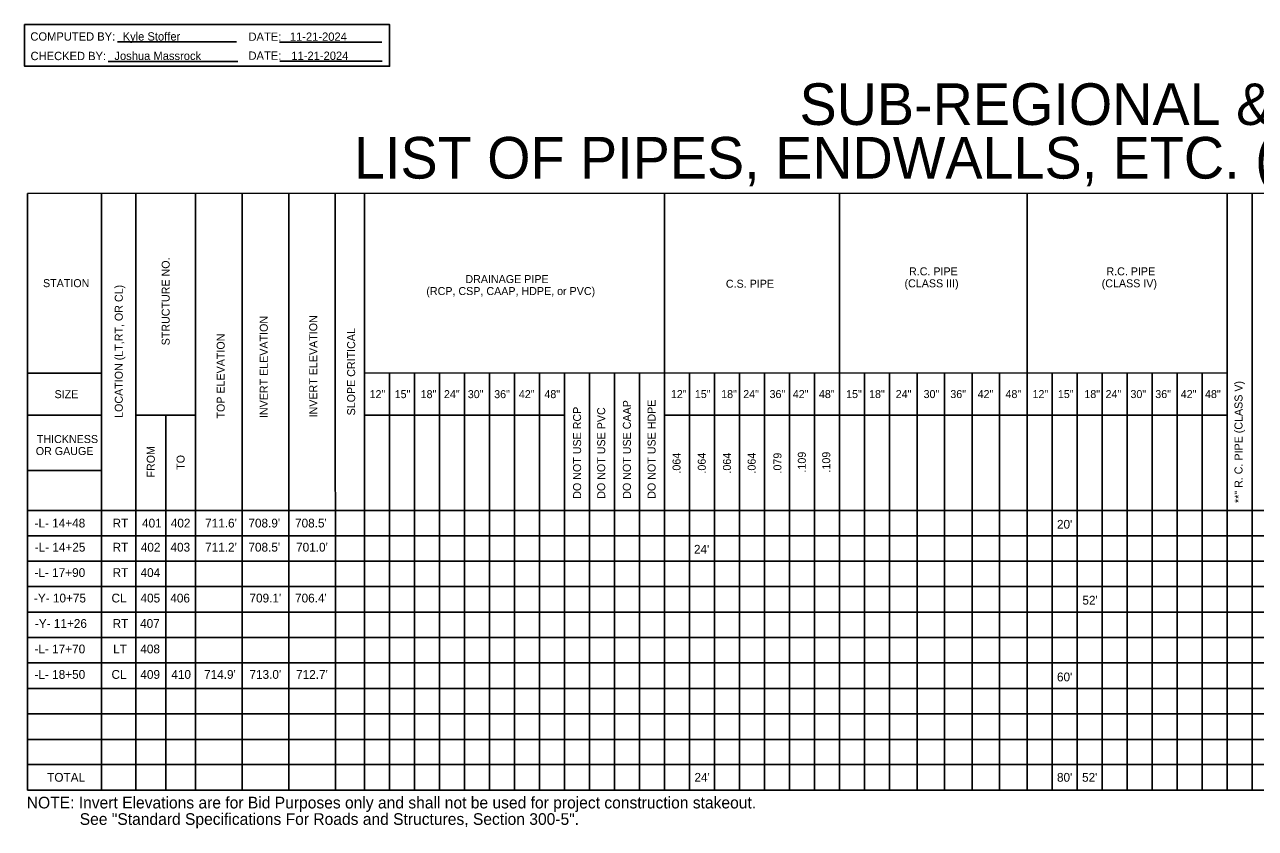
# Model space of a CAD drawing. Extents: x 3532015 to 3532162, y 657889 to 657939.
# Drawn here: x 3532014.8 to 3532088.6, y 657888.8 to 657937.1 of the extents above; entities that cross this region are included whole.
import ezdxf

# ---------------------------------------------------------------- set-up
doc = ezdxf.new("R2010")
doc.units = 0
for name, color, linetype in [('Sheet Block Check By Box CELL', 7, 'Continuous'), ('Sheet Data Field CELL', 7, 'Continuous'), ('Sheet Pipe Summary CELL', 7, 'Continuous'), ('Sheet Pipe Summary Grid CELL', 7, 'Continuous'), ('Sheet Summary Guardrail CELL', 7, 'Continuous')]:
    doc.layers.add(name, color=color, linetype=linetype)

msp = doc.modelspace()

# ---------------------------------------------------------------- linework, layer by layer
at = {"layer": 'Sheet Block Check By Box CELL'}
for p, q in [((3532020.363, 657936.023), (3532027.518, 657936.023)), ((3532030.098, 657936.008), (3532036.238, 657936.008)), ((3532019.818, 657934.853), (3532027.588, 657934.853)), ((3532030.113, 657934.858), (3532036.253, 657934.858))]:
    msp.add_line(p, q, dxfattribs=at)
msp.add_lwpolyline([(3532014.798, 657937.063), (3532036.698, 657937.063), (3532036.698, 657934.563), (3532014.798, 657934.563)], close=True, dxfattribs=at)
at = {"layer": 'Sheet Pipe Summary CELL'}
msp.add_lwpolyline([(3532014.962, 657926.929), (3532014.962, 657891.109)], dxfattribs=at)
at = {"layer": 'Sheet Pipe Summary Grid CELL'}
for p, q in [((3532161.482, 657926.938), (3532014.962, 657926.929)), ((3532019.418, 657891.109), (3532019.416, 657926.929)), ((3532021.473, 657891.109), (3532021.471, 657926.929)), ((3532025.048, 657891.109), (3532025.046, 657926.929)), ((3532027.845, 657891.109), (3532027.843, 657926.929)), ((3532030.643, 657891.109), (3532030.641, 657926.929)), ((3532033.44, 657891.109), (3532033.438, 657926.929)), ((3532035.19, 657891.109), (3532035.188, 657926.929)), ((3532053.19, 657891.109), (3532053.188, 657926.932)), ((3532063.69, 657891.109), (3532063.688, 657926.932)), ((3532074.942, 657891.109), (3532074.938, 657926.94)), ((3532086.942, 657891.109), (3532086.938, 657926.939)), ((3532088.442, 657891.109), (3532088.438, 657926.939)), ((3532019.416, 657916.144), (3532014.962, 657916.144)), ((3532086.939, 657916.152), (3532035.189, 657916.144)), ((3532036.69, 657891.109), (3532036.689, 657916.144)), ((3532038.19, 657891.109), (3532038.189, 657916.144)), ((3532039.69, 657891.109), (3532039.689, 657916.145)), ((3532041.19, 657891.109), (3532041.189, 657916.145)), ((3532042.69, 657891.109), (3532042.689, 657916.145)), ((3532044.19, 657891.109), (3532044.189, 657916.145)), ((3532045.69, 657891.109), (3532045.689, 657916.145)), ((3532047.19, 657891.109), (3532047.189, 657916.145)), ((3532048.69, 657891.109), (3532048.689, 657916.145)), ((3532050.19, 657891.109), (3532050.189, 657916.145)), ((3532051.69, 657891.109), (3532051.689, 657916.145)), ((3532054.69, 657891.109), (3532054.689, 657916.145)), ((3532056.19, 657891.109), (3532056.189, 657916.147)), ((3532057.69, 657891.109), (3532057.689, 657916.146)), ((3532059.19, 657891.109), (3532059.189, 657916.148)), ((3532060.69, 657891.109), (3532060.689, 657916.146)), ((3532062.19, 657891.109), (3532062.189, 657916.148)), ((3532063.69, 657891.109), (3532063.689, 657916.146)), ((3532065.19, 657891.109), (3532065.189, 657916.148)), ((3532066.69, 657891.109), (3532066.689, 657916.149)), ((3532068.34, 657891.109), (3532068.339, 657916.149)), ((3532069.99, 657891.109), (3532069.989, 657916.149)), ((3532071.64, 657891.109), (3532071.639, 657916.149)), ((3532073.29, 657891.109), (3532073.289, 657916.149)), ((3532074.94, 657891.109), (3532074.939, 657916.149)), ((3532076.44, 657891.109), (3532076.439, 657916.149)), ((3532077.94, 657891.109), (3532077.939, 657916.149)), ((3532079.44, 657891.109), (3532079.439, 657916.15)), ((3532080.94, 657891.109), (3532080.939, 657916.15)), ((3532082.44, 657891.109), (3532082.439, 657916.15)), ((3532083.94, 657891.109), (3532083.939, 657916.15)), ((3532085.44, 657891.109), (3532085.439, 657916.15)), ((3532086.94, 657891.109), (3532086.939, 657916.15)), ((3532019.416, 657913.604), (3532014.962, 657913.604)), ((3532025.047, 657913.604), (3532021.472, 657913.604)), ((3532023.262, 657891.109), (3532023.261, 657913.604)), ((3532047.189, 657913.607), (3532035.189, 657913.606)), ((3532086.939, 657913.611), (3532053.189, 657913.608)), ((3532053.19, 657891.109), (3532053.189, 657913.607)), ((3532019.416, 657910.289), (3532014.962, 657910.289)), ((3532161.482, 657907.899), (3532014.962, 657907.899)), ((3532161.482, 657906.369), (3532014.962, 657906.369)), ((3532161.482, 657904.844), (3532014.962, 657904.844)), ((3532161.482, 657903.319), (3532014.962, 657903.319)), ((3532161.482, 657901.789), (3532014.962, 657901.789)), ((3532161.482, 657900.264), (3532014.962, 657900.264)), ((3532161.482, 657898.734), (3532014.962, 657898.734)), ((3532161.482, 657897.204), (3532014.962, 657897.204)), ((3532161.482, 657895.674), (3532014.962, 657895.674)), ((3532161.482, 657894.144), (3532014.962, 657894.144)), ((3532161.482, 657892.639), (3532014.962, 657892.639)), ((3532161.482, 657891.109), (3532014.962, 657891.109))]:
    msp.add_line(p, q, dxfattribs=at)

# ---------------------------------------------------------------- texts
at = {"layer": 'Sheet Block Check By Box CELL'}
for s, height, p in [('COMPUTED BY:', 0.49998, (3532015.143, 657936.098)), ('DATE:', 0.5, (3532028.228, 657936.088)), ('CHECKED BY:', 0.49998, (3532015.153, 657934.928)), ('DATE:', 0.5, (3532028.228, 657934.948))]:
    msp.add_text(s, height=height, dxfattribs=at).set_placement(p)
at = {"layer": 'Sheet Data Field CELL'}
for s, height, p in [('  Kyle Stoffer', 0.50001, (3532020.308, 657936.103)), ('   11-21-2024', 0.49998, (3532030.153, 657936.088)), ('  Joshua Massrock', 0.50001, (3532019.813, 657934.938)), ('   11-21-2024', 0.49998, (3532030.243, 657934.943))]:
    msp.add_text(s, height=height, dxfattribs=at).set_placement(p)
at = {"layer": 'Sheet Pipe Summary CELL'}
for s, height, p in [('SUB-REGIONAL & REGIONAL', 2.5, (3532061.287, 657931.037)), ('LIST OF PIPES, ENDWALLS, ETC. (FOR PIPES 48" & UNDER)', 2.5, (3532034.56, 657927.817)), ('R.C. PIPE', 0.48, (3532067.856, 657922.008)), ('R.C. PIPE', 0.48, (3532079.702, 657922.008)), ('DRAINAGE PIPE', 0.48, (3532041.241, 657921.545)), ('C.S. PIPE', 0.48, (3532056.87, 657921.265)), ('(CLASS III)', 0.48, (3532067.588, 657921.288)), ('(CLASS IV)', 0.48, (3532079.418, 657921.288)), ('(RCP, CSP, CAAP, HDPE, or PVC)', 0.48, (3532038.899, 657920.825)), ('SIZE', 0.48, (3532016.595, 657914.634)), ('12"', 0.48, (3532035.493, 657914.635)), ('15"', 0.48, (3532037, 657914.635)), ('18"', 0.48, (3532038.558, 657914.635)), ('24"', 0.48, (3532039.956, 657914.635)), ('30"', 0.48, (3532041.386, 657914.635)), ('36"', 0.48, (3532042.969, 657914.635)), ('42"', 0.48, (3532044.45, 657914.635)), ('48"', 0.48, (3532045.982, 657914.635)), ('12"', 0.48, (3532053.572, 657914.64)), ('15"', 0.48, (3532055.008, 657914.64)), ('18"', 0.48, (3532056.587, 657914.64)), ('24"', 0.48, (3532057.911, 657914.64)), ('36"', 0.48, (3532059.49, 657914.64)), ('42"', 0.48, (3532060.884, 657914.64)), ('48"', 0.48, (3532062.451, 657914.64)), ('15"', 0.48, (3532064.083, 657914.64)), ('18"', 0.48, (3532065.461, 657914.64)), ('24"', 0.48, (3532067.059, 657914.64)), ('30"', 0.48, (3532068.731, 657914.64)), ('36"', 0.48, (3532070.335, 657914.64)), ('42"', 0.48, (3532071.973, 657914.64)), ('48"', 0.48, (3532073.645, 657914.64)), ('12"', 0.48, (3532075.267, 657914.64)), ('15"', 0.48, (3532076.787, 657914.64)), ('18"', 0.48, (3532078.377, 657914.64)), ('24"', 0.48, (3532079.649, 657914.64)), ('30"', 0.48, (3532081.141, 657914.64)), ('36"', 0.48, (3532082.632, 657914.64)), ('42"', 0.48, (3532084.16, 657914.64)), ('48"', 0.48, (3532085.616, 657914.64)), ('THICKNESS', 0.48, (3532015.532, 657911.939)), ('OR GAUGE', 0.48, (3532015.467, 657911.219)), ('NOTE: Invert Elevations are for Bid Purposes only and shall not be used for project construction stakeout.', 0.7, (3532014.926, 657890.002)), ('See "Standard Specifications For Roads and Structures, Section 300-5".', 0.7, (3532018.103, 657889.015))]:
    msp.add_text(s, height=height, dxfattribs=at).set_placement(p)
for s, rotation, p in [('STRUCTURE NO.', 90, (3532023.501, 657917.804)), ('STATION', 360, (3532015.901, 657921.299)), ('LOCATION (LT,RT, OR CL)', 90, (3532020.686, 657913.449)), ('INVERT ELEVATION', 90, (3532029.387, 657913.439)), ('INVERT ELEVATION', 90, (3532032.353, 657913.479)), ('SLOPE CRITICAL', 90, (3532034.628, 657913.599)), ('TOP ELEVATION', 90, (3532026.801, 657913.411)), ('**" R. C. PIPE (CLASS V)', 90, (3532087.865, 657908.341)), ('DO NOT USE CAAP', 90, (3532051.171, 657908.593)), ('DO NOT USE HDPE', 90, (3532052.652, 657908.593)), ('DO NOT USE RCP', 90, (3532048.183, 657908.593)), ('DO NOT USE PVC', 90, (3532049.629, 657908.593)), ('FROM', 90, (3532022.606, 657909.869)), ('.064', 90, (3532054.15, 657910.107)), ('.064', 90, (3532055.663, 657910.107)), ('.064', 90, (3532057.176, 657910.107)), ('.064', 90, (3532058.657, 657910.107)), ('.079', 90, (3532060.203, 657910.11)), ('.109', 90, (3532061.666, 657910.17)), ('.109', 90, (3532063.131, 657910.17)), ('TO', 90, (3532024.396, 657910.334))]:
    msp.add_text(s, height=0.48, rotation=rotation, dxfattribs=at).set_placement(p)
at = {"layer": 'Sheet Summary Guardrail CELL'}
for s, p in [('-L- 14+48', (3532015.392, 657906.87)), ('RT', (3532020.076, 657906.87)), ('401', (3532021.844, 657906.87)), ('402', (3532023.567, 657906.87)), ("711.6'", (3532025.628, 657906.87)), ("708.9'", (3532028.225, 657906.87)), ("708.5'", (3532031.023, 657906.87)), ("20'", (3532076.734, 657906.797)), ('-L- 14+25', (3532015.402, 657905.423)), ('RT', (3532020.076, 657905.423)), ('402', (3532021.768, 657905.423)), ('403', (3532023.549, 657905.423)), ("711.2'", (3532025.628, 657905.423)), ("708.5'", (3532028.225, 657905.423)), ("701.0'", (3532031.086, 657905.423)), ("24'", (3532054.955, 657905.297)), ('-L- 17+90', (3532015.391, 657903.898)), ('RT', (3532020.076, 657903.898)), ('404', (3532021.754, 657903.898)), ('-Y- 10+75', (3532015.359, 657902.368)), ('CL', (3532020.011, 657902.368)), ('405', (3532021.75, 657902.368)), ('406', (3532023.539, 657902.368)), ("709.1'", (3532028.288, 657902.368)), ("706.4'", (3532031.023, 657902.368)), ("52'", (3532078.26, 657902.242)), ('-Y- 11+26', (3532015.414, 657900.843)), ('RT', (3532020.076, 657900.843)), ('407', (3532021.727, 657900.843)), ('-L- 17+70', (3532015.391, 657899.313)), ('LT', (3532020.107, 657899.313)), ('408', (3532021.74, 657899.313)), ('-L- 18+50', (3532015.391, 657897.783)), ('CL', (3532020.011, 657897.783)), ('409', (3532021.744, 657897.783)), ('410', (3532023.601, 657897.783)), ("714.9'", (3532025.564, 657897.783)), ("713.0'", (3532028.288, 657897.783)), ("712.7'", (3532031.086, 657897.783)), ("60'", (3532076.734, 657897.632)), ('TOTAL', (3532016.151, 657891.605)), ("24'", (3532054.984, 657891.605)), ("80'", (3532076.734, 657891.605)), ("52'", (3532078.239, 657891.605))]:
    msp.add_text(s, height=0.528, dxfattribs=at).set_placement(p)

doc.saveas('drawing.dxf')
